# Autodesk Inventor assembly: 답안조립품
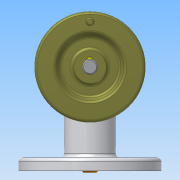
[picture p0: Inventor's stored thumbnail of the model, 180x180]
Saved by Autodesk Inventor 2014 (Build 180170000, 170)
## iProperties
Created: 2018-11
Part Number: 답안조립품
Document SubType Name: Assembly
Designer: 703
Mass: 1865.64 g
Surface Area: 1425.71 cm^2
Volume: 458.854 cm^3
Density: 4.06587 g/cm^3
Author: 703
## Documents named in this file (18)
- C:\Users\user\Desktop\381107V1012\답안조립품.iam
- C:\Users\user\Desktop\381107V1012\V-벨트풀리.ipt
- C:\Users\user\Desktop\381107V1012\가변스프링.ipt
- C:\Users\user\Desktop\381107V1012\개스킷.ipt
- C:\Users\user\Desktop\381107V1012\뒤커버.ipt
- C:\Users\user\Desktop\381107V1012\멈춤나사 M3x8.ipt
- C:\Users\user\Desktop\381107V1012\베어링 6201.ipt
- C:\Users\user\Desktop\381107V1012\베어링 6202.ipt
- C:\Users\user\Desktop\381107V1012\본체.ipt
- C:\Users\user\Desktop\381107V1012\본체커버.ipt
- C:\Users\user\Desktop\381107V1012\볼트 M3x0.5x8.ipt
- C:\Users\user\Desktop\381107V1012\슬라이드.ipt
- C:\Users\user\Desktop\381107V1012\앞커버.ipt
- C:\Users\user\Desktop\381107V1012\오일 실 12 22 7.ipt
- 오일 실 12 22 7.ipt
- C:\Users\user\Desktop\381107V1012\키 4x4x18.ipt
- 키 4x4x18.ipt
- C:\Users\user\Desktop\381107V1012\편심축.ipt
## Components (4 placed, 3 different names)
1. V-벨트풀리:1 — 플러쉬:1
2. 가변스프링:1
3. 개스킷:1
4. 개스킷:2
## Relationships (1: Flush 1)
- 플러쉬:1 [Flush]: V-벨트풀리:1
